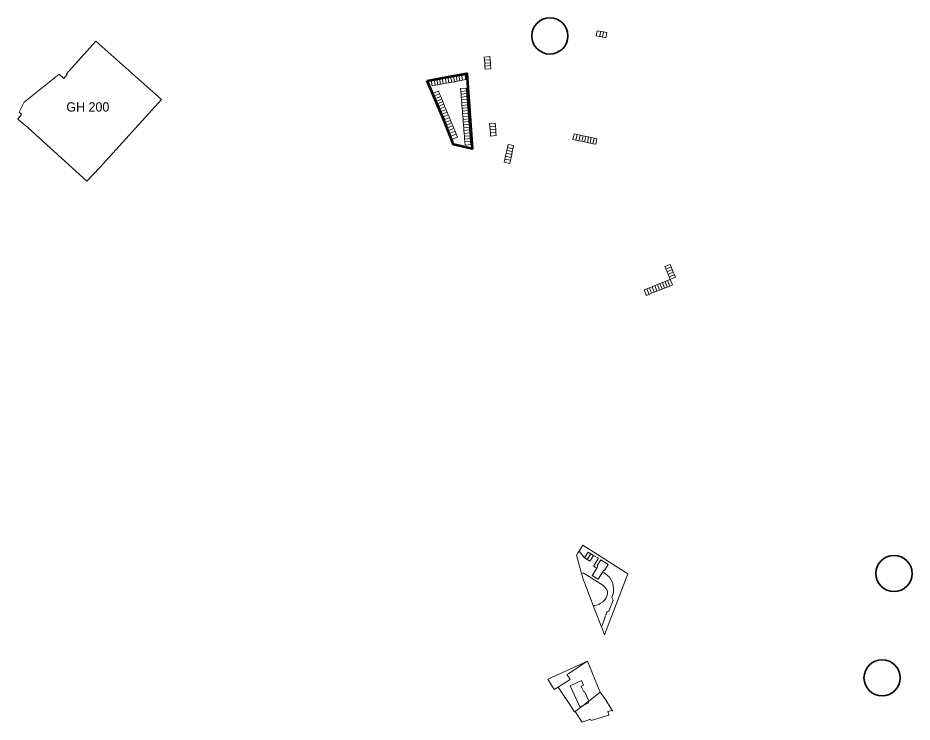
# Model space of a CAD drawing. Extents: x -648438 to -645379, y -1072966 to -1066997.
# Drawn here: x -647855 to -646897, y -1072148 to -1071393 of the extents above; entities that cross this region are included whole.
import ezdxf

# ---------------------------------------------------------------- set-up
doc = ezdxf.new("R2010")
doc.units = 0
doc.header["$LTSCALE"] = 4
doc.layers.add('40', color=7, linetype='Continuous', lineweight=13)
doc.layers.add('60', color=7, linetype='Continuous', lineweight=53)
doc.layers.add('56', color=7, linetype='Continuous')

msp = doc.modelspace()

# ---------------------------------------------------------------- linework, layer by layer
at = {"layer": '40'}
for points in [[(-647235.33, -1071411.77), (-647234.23, -1071406.38), (-647230.64, -1071407.06), (-647231.77, -1071412.48)], [(-647231.77, -1071412.48), (-647230.64, -1071407.06), (-647227.45, -1071407.67), (-647228.58, -1071413.12), (-647230.74, -1071412.69)], [(-647228.58, -1071413.12), (-647227.45, -1071407.67), (-647223.96, -1071408.33), (-647225.1, -1071413.81)], [(-647828.024, -1071525.256), (-647792.998, -1071557.126), (-647781.31, -1071567.79), (-647767.575, -1071553.083), (-647708.18, -1071487.57), (-647701.415, -1071480.15), (-647710.546, -1071472.023), (-647771.82, -1071417.42), (-647803.1, -1071452.66), (-647802.53, -1071453.19), (-647806.15, -1071457.48), (-647810.97, -1071452.92), (-647848.4, -1071482.78), (-647853.77, -1071493.78), (-647851.45, -1071495.96), (-647855.23, -1071501.297), (-647850.55, -1071505.14), (-647844.4, -1071510.2)], [(-647355.38, -1071434.52), (-647349.41, -1071434.06), (-647349.11, -1071437.43), (-647355.12, -1071437.88)], [(-647355.12, -1071437.88), (-647349.11, -1071437.43), (-647348.83, -1071440.61), (-647354.88, -1071441.06)], [(-647354.88, -1071441.06), (-647348.83, -1071440.61), (-647348.55, -1071443.77), (-647354.64, -1071444.22)], [(-647354.64, -1071444.22), (-647348.55, -1071443.77), (-647348.25, -1071447.19), (-647354.38, -1071447.64)], [(-647416.42, -1071460.03), (-647412.36, -1071459.29), (-647411.25, -1071465.39), (-647408.15, -1071464.83), (-647405.25, -1071464.3), (-647402.25, -1071463.76), (-647399.29, -1071463.22), (-647396.29, -1071462.67), (-647393.34, -1071462.14), (-647390.34, -1071461.59), (-647387.43, -1071461.07), (-647384.38, -1071460.51), (-647381.48, -1071459.98), (-647378.63, -1071459.47), (-647375.08, -1071458.82), (-647376.19, -1071452.72), (-647374.2, -1071452.36), (-647368.26, -1071532.99), (-647388.29, -1071528.41), (-647398.64, -1071501.96), (-647413.54, -1071467.53)], [(-647412.36, -1071459.29), (-647409.26, -1071458.73), (-647408.15, -1071464.83), (-647411.25, -1071465.39)], [(-647409.26, -1071458.73), (-647406.36, -1071458.2), (-647405.25, -1071464.3), (-647408.15, -1071464.83)], [(-647406.36, -1071458.2), (-647403.35, -1071457.65), (-647402.25, -1071463.76), (-647405.25, -1071464.3)], [(-647403.35, -1071457.65), (-647400.4, -1071457.12), (-647399.29, -1071463.22), (-647402.25, -1071463.76)], [(-647400.4, -1071457.12), (-647397.4, -1071456.57), (-647396.29, -1071462.67), (-647399.29, -1071463.22)], [(-647397.4, -1071456.57), (-647396.02, -1071456.32), (-647394.45, -1071456.04), (-647393.34, -1071462.14), (-647396.29, -1071462.67)], [(-647394.45, -1071456.04), (-647391.44, -1071455.49), (-647390.34, -1071461.59), (-647393.34, -1071462.14)], [(-647391.44, -1071455.49), (-647388.54, -1071454.96), (-647387.43, -1071461.07), (-647390.34, -1071461.59)], [(-647388.54, -1071454.96), (-647385.49, -1071454.41), (-647384.38, -1071460.51), (-647387.43, -1071461.07)], [(-647385.49, -1071454.41), (-647382.59, -1071453.88), (-647381.48, -1071459.98), (-647384.38, -1071460.51)], [(-647382.59, -1071453.88), (-647379.73, -1071453.36), (-647378.63, -1071459.47), (-647381.48, -1071459.98)], [(-647379.73, -1071453.36), (-647376.19, -1071452.72), (-647375.08, -1071458.82), (-647378.63, -1071459.47)], [(-647410.08, -1071473.29), (-647404.43, -1071471.14), (-647403.23, -1071474.05), (-647408.88, -1071476.2)], [(-647410.08, -1071473.29), (-647408.88, -1071476.2), (-647407.72, -1071479.02), (-647406.58, -1071481.8), (-647405.44, -1071484.57), (-647404.31, -1071487.3), (-647403.17, -1071490.08), (-647402.03, -1071492.85), (-647400.85, -1071495.72), (-647399.67, -1071498.58), (-647398.38, -1071501.73), (-647397.18, -1071504.64), (-647396, -1071507.51), (-647394.84, -1071510.33), (-647393.62, -1071513.29), (-647392.39, -1071516.29), (-647391.1, -1071519.42), (-647389.77, -1071522.65), (-647384.1, -1071520.56), (-647385.43, -1071517.33), (-647386.74, -1071514.14), (-647387.98, -1071511.14), (-647389.2, -1071508.15), (-647390.39, -1071505.26), (-647391.55, -1071502.44), (-647392.75, -1071499.53), (-647393.99, -1071496.51), (-647395.2, -1071493.57), (-647396.35, -1071490.79), (-647397.49, -1071488), (-647398.69, -1071485.1), (-647399.81, -1071482.38), (-647400.93, -1071479.65), (-647402.05, -1071476.92), (-647403.23, -1071474.05), (-647404.43, -1071471.14)], [(-647380.75, -1071468.34), (-647374.73, -1071467.79), (-647374.48, -1071470.93), (-647380.5, -1071471.52)], [(-647380.5, -1071471.52), (-647374.48, -1071470.93), (-647374.25, -1071473.82), (-647380.26, -1071474.46)], [(-647408.88, -1071476.2), (-647403.23, -1071474.05), (-647402.05, -1071476.92), (-647407.72, -1071479.02)], [(-647407.72, -1071479.02), (-647402.05, -1071476.92), (-647400.93, -1071479.65), (-647406.58, -1071481.8)], [(-647406.58, -1071481.8), (-647400.93, -1071479.65), (-647399.81, -1071482.38), (-647405.44, -1071484.57)], [(-647380.26, -1071474.46), (-647374.25, -1071473.82), (-647374.01, -1071476.86), (-647380.03, -1071477.42)], [(-647380.03, -1071477.42), (-647374.01, -1071476.86), (-647373.78, -1071479.85), (-647379.79, -1071480.43)], [(-647379.79, -1071480.43), (-647373.78, -1071479.85), (-647373.54, -1071482.83), (-647379.54, -1071483.47)], [(-647405.44, -1071484.57), (-647399.81, -1071482.38), (-647398.69, -1071485.1), (-647404.31, -1071487.3)], [(-647404.31, -1071487.3), (-647398.69, -1071485.1), (-647397.49, -1071488), (-647403.17, -1071490.08)], [(-647403.17, -1071490.08), (-647397.49, -1071488), (-647396.35, -1071490.79), (-647402.03, -1071492.85)], [(-647379.54, -1071483.47), (-647373.54, -1071482.83), (-647373.3, -1071485.87), (-647379.31, -1071486.41)], [(-647379.31, -1071486.41), (-647373.3, -1071485.87), (-647373.06, -1071488.86), (-647379.06, -1071489.5)], [(-647379.06, -1071489.5), (-647373.06, -1071488.86), (-647372.82, -1071491.9), (-647378.83, -1071492.46)], [(-647402.03, -1071492.85), (-647396.35, -1071490.79), (-647395.2, -1071493.57), (-647400.85, -1071495.72)], [(-647400.85, -1071495.72), (-647395.2, -1071493.57), (-647393.99, -1071496.51), (-647399.67, -1071498.58)], [(-647399.67, -1071498.58), (-647393.99, -1071496.51), (-647392.75, -1071499.53), (-647398.38, -1071501.73)], [(-647398.38, -1071501.73), (-647392.75, -1071499.53), (-647391.55, -1071502.44), (-647397.18, -1071504.64)], [(-647378.83, -1071492.46), (-647372.82, -1071491.9), (-647372.59, -1071494.89), (-647378.59, -1071495.42)], [(-647378.59, -1071495.42), (-647372.59, -1071494.89), (-647372.35, -1071497.83), (-647378.36, -1071498.36)], [(-647378.36, -1071498.36), (-647372.35, -1071497.83), (-647372.11, -1071500.87), (-647378.11, -1071501.45)], [(-647397.18, -1071504.64), (-647391.55, -1071502.44), (-647390.39, -1071505.26), (-647396, -1071507.51)], [(-647396, -1071507.51), (-647390.39, -1071505.26), (-647389.2, -1071508.15), (-647394.84, -1071510.33)], [(-647394.84, -1071510.33), (-647389.2, -1071508.15), (-647387.98, -1071511.14), (-647393.62, -1071513.29)], [(-647378.11, -1071501.45), (-647372.11, -1071500.87), (-647371.88, -1071503.86), (-647377.88, -1071504.34)], [(-647377.88, -1071504.34), (-647371.88, -1071503.86), (-647371.64, -1071506.85), (-647377.64, -1071507.38)], [(-647377.64, -1071507.38), (-647371.64, -1071506.85), (-647371.4, -1071509.89), (-647377.4, -1071510.41)], [(-647349.65, -1071505.87), (-647343.62, -1071505.45), (-647343.36, -1071508.84), (-647349.38, -1071509.27)], [(-647349.38, -1071509.27), (-647343.36, -1071508.84), (-647343.12, -1071512.11), (-647349.12, -1071512.57)], [(-647393.62, -1071513.29), (-647387.98, -1071511.14), (-647386.74, -1071514.14), (-647392.39, -1071516.29)], [(-647392.39, -1071516.29), (-647386.74, -1071514.14), (-647385.43, -1071517.33), (-647391.1, -1071519.42)], [(-647391.1, -1071519.42), (-647385.43, -1071517.33), (-647384.1, -1071520.56), (-647389.77, -1071522.65)], [(-647377.4, -1071510.41), (-647371.4, -1071509.89), (-647371.17, -1071512.8), (-647377.16, -1071513.37)], [(-647377.16, -1071513.37), (-647371.17, -1071512.8), (-647370.94, -1071515.77), (-647376.92, -1071516.39)], [(-647376.92, -1071516.39), (-647370.94, -1071515.77), (-647370.69, -1071518.9), (-647376.68, -1071519.45)], [(-647376.68, -1071519.45), (-647370.69, -1071518.9), (-647370.45, -1071521.94), (-647376.43, -1071522.5)], [(-647349.12, -1071512.57), (-647343.12, -1071512.11), (-647342.88, -1071515.33), (-647348.86, -1071515.83)], [(-647348.86, -1071515.83), (-647342.88, -1071515.33), (-647342.85, -1071515.73), (-647342.62, -1071518.75), (-647348.59, -1071519.28), (-647348.84, -1071516.15)], [(-647260.51, -1071522.84), (-647259.23, -1071516.92), (-647256.02, -1071517.61), (-647257.3, -1071523.53)], [(-647257.3, -1071523.53), (-647256.02, -1071517.61), (-647252.68, -1071518.33), (-647253.96, -1071524.25)], [(-647253.96, -1071524.25), (-647252.68, -1071518.33), (-647249.55, -1071519), (-647250.83, -1071524.93)], [(-647250.83, -1071524.93), (-647249.55, -1071519), (-647246.57, -1071519.65), (-647247.85, -1071525.57)], [(-647376.43, -1071522.5), (-647370.45, -1071521.94), (-647370.21, -1071524.98), (-647376.19, -1071525.6)], [(-647376.19, -1071525.6), (-647370.21, -1071524.98), (-647369.94, -1071528.37), (-647375.92, -1071528.94)], [(-647330.67, -1071531.69), (-647329.96, -1071528.31), (-647324.04, -1071529.54), (-647324.74, -1071532.92)], [(-647247.85, -1071525.57), (-647246.57, -1071519.65), (-647243.59, -1071520.29), (-647244.87, -1071526.21)], [(-647244.87, -1071526.21), (-647243.59, -1071520.29), (-647240.73, -1071520.91), (-647242, -1071526.83)], [(-647242, -1071526.83), (-647240.73, -1071520.91), (-647237.77, -1071521.54), (-647239.05, -1071527.47)], [(-647239.05, -1071527.47), (-647237.77, -1071521.54), (-647234.6, -1071522.23), (-647235.87, -1071528.14)], [(-647332.59, -1071540.94), (-647331.94, -1071537.81), (-647326.02, -1071539.04), (-647326.67, -1071542.17)], [(-647331.94, -1071537.81), (-647331.31, -1071534.77), (-647325.38, -1071536), (-647326.02, -1071539.04)], [(-647331.31, -1071534.77), (-647330.67, -1071531.69), (-647324.74, -1071532.92), (-647325.38, -1071536)], [(-647333.94, -1071547.4), (-647333.23, -1071544.02), (-647327.31, -1071545.25), (-647328.01, -1071548.63)], [(-647333.23, -1071544.02), (-647332.59, -1071540.94), (-647326.67, -1071542.17), (-647327.31, -1071545.25)], [(-647161.79, -1071659.21), (-647158.77, -1071657.96), (-647158.56, -1071657.87), (-647156.24, -1071656.9), (-647155.09, -1071659.68), (-647160.64, -1071661.98)], [(-647160.64, -1071661.98), (-647155.09, -1071659.68), (-647153.94, -1071662.45), (-647159.49, -1071664.75)], [(-647159.49, -1071664.75), (-647153.94, -1071662.45), (-647152.79, -1071665.24), (-647158.33, -1071667.52)], [(-647158.33, -1071667.52), (-647152.79, -1071665.24), (-647151.64, -1071668.01), (-647157.18, -1071670.29)], [(-647157.18, -1071670.29), (-647151.64, -1071668.01), (-647150.49, -1071670.79), (-647153.03, -1071671.86), (-647156.03, -1071673.06)], [(-647181.13, -1071683.14), (-647178.35, -1071682.02), (-647176.02, -1071687.96), (-647178.8, -1071689.08)], [(-647178.35, -1071682.02), (-647175.47, -1071680.87), (-647173.15, -1071686.79), (-647176.02, -1071687.96)], [(-647175.47, -1071680.87), (-647172.67, -1071679.74), (-647170.35, -1071685.66), (-647173.15, -1071686.79)], [(-647172.67, -1071679.74), (-647169.9, -1071678.63), (-647167.58, -1071684.54), (-647170.35, -1071685.66)], [(-647169.9, -1071678.63), (-647167.16, -1071677.53), (-647164.85, -1071683.43), (-647167.58, -1071684.54)], [(-647167.16, -1071677.53), (-647164.43, -1071676.43), (-647162.12, -1071682.32), (-647164.85, -1071683.43)], [(-647164.43, -1071676.43), (-647161.69, -1071675.33), (-647159.38, -1071681.21), (-647162.12, -1071682.32)], [(-647161.69, -1071675.33), (-647159, -1071674.25), (-647156.69, -1071680.12), (-647159.38, -1071681.21)], [(-647159, -1071674.25), (-647156.03, -1071673.06), (-647153.73, -1071678.92), (-647156.69, -1071680.12)], [(-647184.06, -1071684.32), (-647181.13, -1071683.14), (-647178.8, -1071689.08), (-647181.72, -1071690.27), (-647181.96, -1071689.71)], [(-647253.85, -1071964.38), (-647249.92, -1071958.12), (-647201.53, -1071988.71), (-647226.41, -1072054.11), (-647227.91, -1072050.19), (-647229.6, -1072045.76), (-647229.16, -1072044.37), (-647224.15, -1072030.05), (-647221.82, -1072028.52), (-647217.43, -1072016.97), (-647218.55, -1072014.16), (-647217.05, -1072008.9), (-647216.8, -1072005.34), (-647217.63, -1071998.93), (-647221.36, -1071992.47), (-647225.69, -1071988.49), (-647228.46, -1071986.71), (-647227.17, -1071984.67), (-647226.54, -1071985.07), (-647222.58, -1071978.95), (-647230.39, -1071973.9), (-647234.35, -1071980.03), (-647233.59, -1071980.52), (-647234.93, -1071982.62), (-647238.29, -1071980.49), (-647233, -1071972.13), (-647238.25, -1071968.97), (-647241.15, -1071967.18), (-647244.04, -1071965.39), (-647248.06, -1071971.63)], [(-647248.06, -1071971.63), (-647244.04, -1071965.39), (-647241.15, -1071967.18), (-647245.13, -1071973.46)], [(-647245.13, -1071973.46), (-647241.15, -1071967.18), (-647238.25, -1071968.97), (-647242.19, -1071975.29)], [(-647239.89, -1071990.42), (-647234.93, -1071982.62), (-647233.59, -1071980.52), (-647234.35, -1071980.03), (-647230.39, -1071973.9), (-647222.58, -1071978.95), (-647226.54, -1071985.07), (-647227.17, -1071984.67), (-647228.46, -1071986.71), (-647233.43, -1071994.51)], [(-647251.05, -1071988.58), (-647249.97, -1071987.94), (-647248.83, -1071988.03), (-647246.39, -1071989.5), (-647228.51, -1072000.87), (-647226.51, -1072002.59), (-647225.2, -1072004.39), (-647224.06, -1072005.94), (-647223.37, -1072007.74), (-647223.28, -1072010.27), (-647223.89, -1072012.73), (-647224.85, -1072014.61), (-647226.59, -1072016.98), (-647228.51, -1072018.86), (-647230.69, -1072020.42), (-647232.52, -1072021.56), (-647234.97, -1072022.3), (-647237.23, -1072022.71), (-647238.59, -1072022.61), (-647248.15, -1071998.18), (-647249.16, -1071995.59)], [(-647287.34, -1072101.88), (-647244.88, -1072082.33), (-647250.54, -1072086.1), (-647264.71, -1072095.53), (-647266.76, -1072096.89), (-647265.08, -1072099.42), (-647264.55, -1072100.22), (-647263.39, -1072101.97), (-647272.07, -1072107.63), (-647276.11, -1072110.44), (-647280.56, -1072112.9)], [(-647276.11, -1072110.44), (-647272.07, -1072107.63), (-647263.39, -1072101.97), (-647264.55, -1072100.22), (-647265.08, -1072099.42), (-647266.76, -1072096.89), (-647264.71, -1072095.53), (-647250.54, -1072086.1), (-647244.88, -1072082.33), (-647241.57, -1072090.33), (-647237.14, -1072101.05), (-647236.46, -1072102.7), (-647231.03, -1072115.83), (-647243.31, -1072125.2), (-647247.66, -1072115.5), (-647248.83, -1072115.4), (-647251.51, -1072109.52), (-647251.58, -1072109.38), (-647249.01, -1072108.16), (-647251.2, -1072103.31), (-647263.2, -1072108.76), (-647252.96, -1072131.44), (-647249.39, -1072129.84), (-647257.88, -1072136.31), (-647258.54, -1072136.82), (-647263.07, -1072130.02), (-647272.55, -1072115.78)], [(-647263.2, -1072108.76), (-647251.2, -1072103.31), (-647249.01, -1072108.16), (-647251.58, -1072109.38), (-647251.51, -1072109.52), (-647248.83, -1072115.4), (-647247.66, -1072115.5), (-647243.31, -1072125.2), (-647244.15, -1072125.84), (-647249.39, -1072129.84), (-647252.96, -1072131.44)], [(-647257.88, -1072136.31), (-647250.31, -1072147.84), (-647241.44, -1072144.76), (-647240.91, -1072146.14), (-647221.74, -1072140.53), (-647221.92, -1072140.03), (-647222.92, -1072136.43), (-647218.57, -1072135.49), (-647217.78, -1072135.69), (-647219.23, -1072133.42), (-647224.78, -1072124.79), (-647227.37, -1072121.08), (-647231.03, -1072115.83), (-647243.31, -1072125.2), (-647243.17, -1072125.51), (-647243.86, -1072126.48), (-647243.56, -1072127.22), (-647244.39, -1072127.59), (-647249.39, -1072129.84)], [(-647249.39, -1072129.84), (-647244.15, -1072125.84), (-647243.31, -1072125.2), (-647243.17, -1072125.51), (-647243.86, -1072126.48), (-647243.56, -1072127.22), (-647244.39, -1072127.59)]]:
    msp.add_lwpolyline(points, close=True, dxfattribs=at)
for points in [[(-647374.25, -1071473.82), (-647374.48, -1071470.93), (-647374.73, -1071467.79), (-647380.75, -1071468.34)], [(-647380.75, -1071468.34), (-647380.5, -1071471.52), (-647380.26, -1071474.46), (-647380.03, -1071477.42), (-647379.79, -1071480.43), (-647379.54, -1071483.47), (-647379.31, -1071486.41), (-647379.06, -1071489.5), (-647378.83, -1071492.46), (-647378.59, -1071495.42), (-647378.36, -1071498.36), (-647378.11, -1071501.45), (-647377.88, -1071504.34), (-647377.64, -1071507.38), (-647377.4, -1071510.41), (-647377.16, -1071513.37), (-647376.92, -1071516.39), (-647376.68, -1071519.45), (-647376.43, -1071522.5), (-647376.19, -1071525.6), (-647375.92, -1071528.94), (-647369.94, -1071528.37), (-647370.21, -1071524.98), (-647370.45, -1071521.94), (-647370.69, -1071518.9), (-647370.94, -1071515.77), (-647371.17, -1071512.8), (-647371.4, -1071509.89), (-647371.64, -1071506.85), (-647371.88, -1071503.86), (-647372.11, -1071500.87), (-647372.35, -1071497.83), (-647372.59, -1071494.89), (-647372.82, -1071491.9), (-647373.06, -1071488.86), (-647373.3, -1071485.87), (-647373.54, -1071482.83), (-647373.78, -1071479.85), (-647374.01, -1071476.86), (-647374.25, -1071473.82)], [(-647256.53, -1071968.64), (-647255.04, -1071966.27), (-647253.85, -1071964.38), (-647248.06, -1071971.63), (-647245.13, -1071973.46), (-647242.19, -1071975.29), (-647238.25, -1071968.97), (-647233, -1071972.13), (-647238.29, -1071980.49), (-647234.93, -1071982.62), (-647239.89, -1071990.42), (-647233.43, -1071994.51), (-647228.46, -1071986.71), (-647225.69, -1071988.49), (-647221.36, -1071992.47), (-647217.63, -1071998.93), (-647216.8, -1072005.34), (-647217.05, -1072008.9), (-647218.55, -1072014.16), (-647217.43, -1072016.97), (-647221.82, -1072028.52), (-647224.15, -1072030.05), (-647229.16, -1072044.37), (-647229.6, -1072045.76), (-647229.98, -1072044.76), (-647238.59, -1072022.61), (-647237.23, -1072022.71), (-647234.97, -1072022.3), (-647232.52, -1072021.56), (-647230.69, -1072020.42), (-647228.51, -1072018.86), (-647226.59, -1072016.98), (-647224.85, -1072014.61), (-647223.89, -1072012.73), (-647223.28, -1072010.27), (-647223.37, -1072007.74), (-647224.06, -1072005.94), (-647225.2, -1072004.39), (-647226.51, -1072002.59), (-647228.51, -1072000.87)], [(-647228.51, -1072000.87), (-647246.39, -1071989.5), (-647248.83, -1071988.03), (-647249.97, -1071987.94), (-647251.05, -1071988.58), (-647256.53, -1071968.64)]]:
    msp.add_lwpolyline(points, dxfattribs=at)
at = {"layer": '40', "lineweight": 35}
for centre in [(-647285.098, -1071411.962), (-646916.285, -1071988.453), (-646929.031, -1072100.343)]:
    msp.add_circle(centre, 19.412, dxfattribs=at)
at = {"layer": '60'}
msp.add_lwpolyline([(-647416.42, -1071460.03), (-647396.02, -1071456.32), (-647374.2, -1071452.36), (-647368.26, -1071532.99), (-647388.29, -1071528.41), (-647398.64, -1071501.96), (-647413.54, -1071467.53)], close=True, dxfattribs=at)

# ---------------------------------------------------------------- texts
at = {"layer": '56'}
msp.add_text('GH 200', height=10, dxfattribs=at).set_placement((-647803.309, -1071493.062))

doc.saveas('drawing.dxf')
